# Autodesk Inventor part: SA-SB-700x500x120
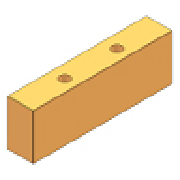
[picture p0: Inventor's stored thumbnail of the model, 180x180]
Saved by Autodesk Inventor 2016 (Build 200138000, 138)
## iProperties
Created: 2015-02
Part Number: SA-SB-700x500x120
Material: S 55 C
Description: Spacer Block
Document SubType Name: Modeling
Designer: Sandeep
Standard Revision: 1
Manufacturer: FUTABA
Language: en-US
Size Designation: 700x500x120
Categories: <MemberInstance><Categories><Category DisplayName="Mold" InternalName="349578f2-f4d4-4954-8c09-8e99297a61c0" Mnemonic="MOLD"><Category DisplayName="Mold Plates"
Density: 7.85 g/cm^3
Appearance: Orange (Pale)
IsCustomPart: 1
Author: Sandeep
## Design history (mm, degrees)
sketch "Sketch1"
  geometry: L1 (-162, 350)-(-250, 350); L2 (-250, 350)-(-250, -350); L3 (-250, -350)-(-162, -350); L4 (-162, -350)-(-162, 350); L5 (250, 350)-(250, -350); L6 (162, -350)-(162, 350); L7 (162, 350)-(250, 350); L8 (162, -350)-(250, -350); 5 further points
  constraints: 16 end point, 3 parallel, 2 horizontal alignment, 2 midpoint, 2 perpendicular, 1 horizontal, 1 vertical
  dimensions: "d85" = 700 distance between parallel lines of L3 L1 (= L); "d86" = 88 distance between parallel lines of L4 L2 (= W_); "d88" = 88 distance between parallel lines of L5 L6 (= W_); "d89" = 250 distance from line of point (0, 0) L2 (= 0.5 x M_W); "d93" = 700 distance between parallel lines of L8 L7 (= L); "d94" = 250 distance from line of point (0, 0) L5 (= 0.5 x M_W); "d98" = 243 vertical distance of point (-205, 243) point (0, 0) (= 0.5 x S1_L); "d100" = 205 horizontal distance of point (-205, 243) point (0, 0) (= 0.5 x S1_W); "d101" = 205 horizontal distance of point (205, 243) point (0, 0) (= 0.5 x S1_W); "d102" = 243 vertical distance of point (0, 0) point (205, 243) (= 0.5 x S1_L)
extrude "Extrusion1" new body sketch "Sketch1" distance "d20" = 120 (= H_); taper "d30" = 0 deg
extrude "Extrusion2" join sketch "Sketch1" distance "d95" = 120 (= H_); taper "d96" = 0 deg
workplane "Work Plane2"
body "Solid1"
hole "Hole1" sketch "Sketch1" diameter "d129" = 18 (= S1_d1); stored, may be unused: countersink angle "d133" = 90 deg, drill point angle "d135" = 0 deg; dims "d130" = 6, "d131" = 4, "d132" = 2, "d134" = 120 (= H_)
pattern_linear "Rectangular Pattern1" dims "d156" = 243 (computed from S1_L, Ns)
hole "Hole2" sketch "Sketch1" diameter "d122" = 18 (= S1_d1); stored, may be unused: countersink angle "d126" = 90 deg, drill point angle "d128" = 0 deg; dims "d123" = 6, "d124" = 4, "d125" = 2, "d127" = 120 (= H_)
pattern_linear "Rectangular Pattern2" dims "d153" = 243 (computed from S1_L, Ns)
workplane "Work Plane1"
chamfer "Chamfer1" distance "d157" = 0.5; stored, may be unused: second distance "d158" = 2, angle "d159" = 45 deg
chamfer "Chamfer2" distance "d160" = 0.5; stored, may be unused: second distance "d161" = 2, angle "d162" = 45 deg
other parameters: "L" = 700 [user parameter; used in 2 equation terms], "W_" = 88 [user parameter; used in 2 equation terms], "H_" = 120 [user parameter; used in 5 equation terms], "S1_L" = 486 [user parameter; used in 4 equation terms], "S1_d1" = 18 [user parameter; used in 2 equation terms], "d164" = 0
